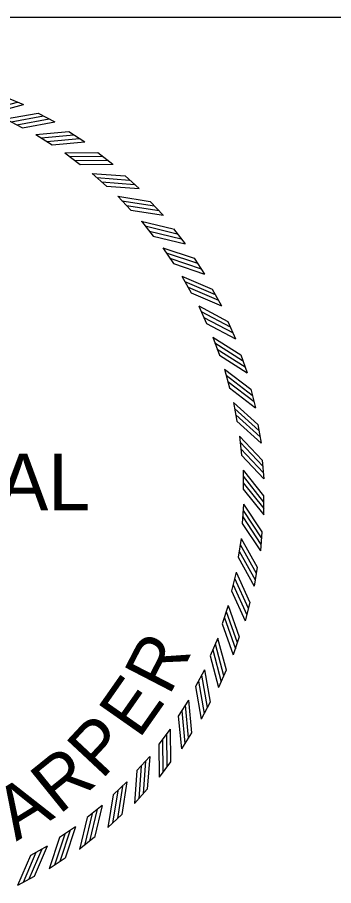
# Model space of a CAD drawing. Extents: x 16 to 1228740, y 11 to 152440.
# Drawn here: x 17.7982 to 17.8608, y 10.8266 to 10.9986 of the extents above; entities that cross this region are included whole.
import ezdxf

# ---------------------------------------------------------------- set-up
doc = ezdxf.new("R2010")
doc.units = 0
doc.layers.add('R_No Plot', color=7, linetype='Continuous')
doc.layers.add('STAMP_FRED', color=7, linetype='Continuous')

msp = doc.modelspace()

# ---------------------------------------------------------------- linework, layer by layer
at = {"layer": 'R_No Plot'}
msp.add_line((17.888, 10.99864), (17.47349, 10.99864), dxfattribs=at)
at = {"layer": 'STAMP_FRED'}
for p, q in [((17.79591, 10.98283), (17.79938, 10.98135)), ((17.79585, 10.97854), (17.79919, 10.97677)), ((17.80228, 10.97968), (17.80561, 10.97791)), ((17.80187, 10.9754), (17.80505, 10.97337)), ((17.80836, 10.97601), (17.81154, 10.97398)), ((17.8076, 10.97178), (17.81061, 10.96949)), ((17.81413, 10.97185), (17.81712, 10.96956)), ((17.81302, 10.9677), (17.81582, 10.96517)), ((17.81952, 10.96723), (17.82232, 10.9647)), ((17.81808, 10.96319), (17.82066, 10.96043)), ((17.82452, 10.96218), (17.8271, 10.95943)), ((17.82275, 10.95827), (17.8251, 10.95531)), ((17.82909, 10.95673), (17.83143, 10.95378)), ((17.827, 10.95298), (17.82909, 10.94984)), ((17.83319, 10.95093), (17.83528, 10.94779)), ((17.83079, 10.94737), (17.83262, 10.94406)), ((17.83679, 10.94481), (17.83862, 10.94151)), ((17.83411, 10.94145), (17.83566, 10.93801)), ((17.83988, 10.93841), (17.84143, 10.93497)), ((17.83694, 10.93529), (17.8382, 10.93172)), ((17.84243, 10.93177), (17.84369, 10.92822)), ((17.83924, 10.92891), (17.8402, 10.92525)), ((17.84443, 10.92495), (17.84538, 10.92131)), ((17.841, 10.92236), (17.84166, 10.91864)), ((17.84585, 10.91799), (17.8465, 10.91428)), ((17.84222, 10.91569), (17.84257, 10.91193)), ((17.84669, 10.91093), (17.84704, 10.90718)), ((17.84289, 10.90894), (17.84292, 10.90516)), ((17.84695, 10.90383), (17.84698, 10.90006)), ((17.843, 10.90216), (17.84272, 10.89839)), ((17.84662, 10.89673), (17.84634, 10.89297)), ((17.84254, 10.89539), (17.84195, 10.89166)), ((17.8457, 10.88969), (17.84512, 10.88596)), ((17.84153, 10.88869), (17.84064, 10.88501)), ((17.83997, 10.88209), (17.83877, 10.8785)), ((17.84421, 10.88274), (17.84332, 10.87908)), ((17.83787, 10.87564), (17.83638, 10.87216)), ((17.84215, 10.87594), (17.84096, 10.87236)), ((17.83524, 10.86939), (17.83347, 10.86605)), ((17.83953, 10.86933), (17.83805, 10.86587)), ((17.8321, 10.86337), (17.83007, 10.86019)), ((17.83638, 10.86296), (17.83461, 10.85963)), ((17.82848, 10.85764), (17.82619, 10.85464)), ((17.83271, 10.85688), (17.83068, 10.8537)), ((17.8244, 10.85222), (17.82187, 10.84942)), ((17.82855, 10.85112), (17.82626, 10.84812)), ((17.81989, 10.84716), (17.81713, 10.84458)), ((17.82393, 10.84572), (17.8214, 10.84292)), ((17.81497, 10.84249), (17.81201, 10.84014)), ((17.81888, 10.84072), (17.81613, 10.83814)), ((17.80968, 10.83824), (17.80654, 10.83615)), ((17.81343, 10.83615), (17.81048, 10.83381)), ((17.80407, 10.83445), (17.80076, 10.83262)), ((17.80763, 10.83205), (17.80449, 10.82996)), ((17.80151, 10.82845), (17.79821, 10.82662))]:
    msp.add_line(p, q, dxfattribs=at)
for points in [[(17.79192, 10.98019), (17.79823, 10.98185)], [(17.79307, 10.97968), (17.79938, 10.98135)], [(17.79585, 10.97854), (17.80227, 10.97968)], [(17.79692, 10.97796), (17.80334, 10.9791)], [(17.79809, 10.97737), (17.80451, 10.97851)], [(17.79919, 10.97678), (17.80561, 10.97791)], [(17.80186, 10.9754), (17.80836, 10.97601)], [(17.80288, 10.97474), (17.80937, 10.97535)], [(17.804, 10.97406), (17.81049, 10.97466)], [(17.80505, 10.97337), (17.81154, 10.97398)], [(17.8076, 10.97178), (17.81412, 10.97185)], [(17.80855, 10.97104), (17.81508, 10.97111)], [(17.80961, 10.97027), (17.81613, 10.97033)], [(17.8106, 10.9695), (17.81713, 10.96956)], [(17.81301, 10.9677), (17.81952, 10.96723)], [(17.81391, 10.96688), (17.82041, 10.96641)], [(17.8149, 10.96603), (17.8214, 10.96555)], [(17.81582, 10.96517), (17.82233, 10.9647)], [(17.81807, 10.96319), (17.82452, 10.96218)], [(17.81889, 10.9623), (17.82534, 10.96129)], [(17.81981, 10.96136), (17.82626, 10.96035)], [(17.82066, 10.96044), (17.82711, 10.95943)], [(17.82274, 10.95827), (17.82908, 10.95674)], [(17.82349, 10.95731), (17.82983, 10.95578)], [(17.82433, 10.95631), (17.83066, 10.95477)], [(17.8251, 10.95532), (17.83144, 10.95378)], [(17.82699, 10.95299), (17.83318, 10.95093)], [(17.82766, 10.95197), (17.83385, 10.94992)], [(17.82841, 10.9509), (17.8346, 10.94884)], [(17.82909, 10.94985), (17.83528, 10.94779)], [(17.83079, 10.94737), (17.83679, 10.94481)], [(17.83137, 10.9463), (17.83737, 10.94374)], [(17.83203, 10.94517), (17.83803, 10.94261)], [(17.83262, 10.94406), (17.83862, 10.94151)], [(17.83411, 10.94146), (17.83988, 10.93841)], [(17.8346, 10.94034), (17.84037, 10.9373)], [(17.83516, 10.93916), (17.84093, 10.93612)], [(17.83567, 10.93801), (17.84143, 10.93497)], [(17.83693, 10.93529), (17.84243, 10.93178)], [(17.83732, 10.93414), (17.84282, 10.93063)], [(17.83779, 10.93292), (17.84329, 10.9294)], [(17.8382, 10.93173), (17.84369, 10.92822)], [(17.83923, 10.92891), (17.84442, 10.92496)], [(17.83953, 10.92773), (17.84472, 10.92378)], [(17.83989, 10.92647), (17.84508, 10.92252)], [(17.8402, 10.92526), (17.84539, 10.9213)], [(17.841, 10.92236), (17.84584, 10.91799)], [(17.8412, 10.92117), (17.84604, 10.9168)], [(17.84146, 10.91988), (17.8463, 10.91551)], [(17.84166, 10.91864), (17.84651, 10.91427)], [(17.84222, 10.91569), (17.84669, 10.91094)], [(17.84232, 10.91448), (17.84679, 10.90973)], [(17.84247, 10.91318), (17.84694, 10.90843)], [(17.84257, 10.91193), (17.84704, 10.90718)], [(17.84289, 10.90894), (17.84695, 10.90384)], [(17.84289, 10.90773), (17.84695, 10.90262)], [(17.84293, 10.90642), (17.84699, 10.90131)], [(17.84293, 10.90517), (17.84699, 10.90006)], [(17.84289, 10.90095), (17.84652, 10.89553)], [(17.84299, 10.90216), (17.84662, 10.89674)], [(17.84283, 10.89965), (17.84645, 10.89422)], [(17.84272, 10.89839), (17.84634, 10.89297)], [(17.84234, 10.8942), (17.8455, 10.8885)], [(17.84254, 10.8954), (17.8457, 10.88969)], [(17.84216, 10.8929), (17.84533, 10.8872)], [(17.84196, 10.89166), (17.84512, 10.88596)], [(17.84123, 10.88752), (17.84391, 10.88157)], [(17.84153, 10.88869), (17.84421, 10.88274)], [(17.84095, 10.88624), (17.84363, 10.88029)], [(17.84064, 10.88502), (17.84332, 10.87907)], [(17.83997, 10.88209), (17.84215, 10.87594)], [(17.83957, 10.88094), (17.84175, 10.8748)], [(17.83878, 10.87851), (17.84096, 10.87236)], [(17.83919, 10.87969), (17.84137, 10.87355)], [(17.83786, 10.87564), (17.83953, 10.86934)], [(17.83689, 10.87332), (17.83855, 10.86701)], [(17.83738, 10.87453), (17.83904, 10.86823)], [(17.83638, 10.87217), (17.83805, 10.86586)], [(17.83466, 10.86833), (17.8358, 10.8619)], [(17.83524, 10.86939), (17.83638, 10.86297)], [(17.83407, 10.86715), (17.83521, 10.86073)], [(17.83348, 10.86605), (17.83461, 10.85963)], [(17.8321, 10.86338), (17.83271, 10.85688)], [(17.83076, 10.86124), (17.83136, 10.85475)], [(17.83144, 10.86236), (17.83204, 10.85587)], [(17.83007, 10.86019), (17.83068, 10.8537)], [(17.82774, 10.85669), (17.82781, 10.85016)], [(17.82848, 10.85764), (17.82855, 10.85112)], [(17.8262, 10.85464), (17.82626, 10.84811)], [(17.82697, 10.85563), (17.82703, 10.84911)], [(17.82358, 10.85134), (17.82311, 10.84483)], [(17.8244, 10.85223), (17.82393, 10.84572)], [(17.82187, 10.84942), (17.8214, 10.84291)], [(17.82272, 10.85034), (17.82225, 10.84384)], [(17.819, 10.84635), (17.81799, 10.8399)], [(17.81989, 10.84717), (17.81888, 10.84072)], [(17.81714, 10.84458), (17.81613, 10.83813)], [(17.81806, 10.84543), (17.81705, 10.83898)], [(17.81497, 10.8425), (17.81344, 10.83616)], [(17.81301, 10.84092), (17.81147, 10.83458)], [(17.81401, 10.84175), (17.81248, 10.83541)], [(17.81202, 10.84014), (17.81048, 10.8338)], [(17.80867, 10.83759), (17.80662, 10.83139)], [(17.80969, 10.83825), (17.80763, 10.83206)], [(17.80655, 10.83615), (17.80449, 10.82996)], [(17.8076, 10.83683), (17.80554, 10.83064)], [(17.803, 10.83387), (17.80044, 10.82787)], [(17.80407, 10.83445), (17.80151, 10.82845)], [(17.80076, 10.83262), (17.79821, 10.82662)], [(17.80187, 10.83321), (17.79931, 10.82721)]]:
    msp.add_lwpolyline(points, dxfattribs=at)

# ---------------------------------------------------------------- texts
msp.add_text('PROFESSIONAL', height=0.0111934, dxfattribs=at).set_placement((17.69618, 10.901))
for s, rotation, p in [('R', 62.6418, (17.82825, 10.86405)), ('E', 54.981, (17.82229, 10.85549)), ('P', 46.9554, (17.81488, 10.84746)), ('R', 38.9298, (17.80643, 10.84054)), ('A', 31.6338, (17.79797, 10.83533))]:
    msp.add_text(s, height=0.01042, rotation=rotation, dxfattribs=at).set_placement(p)

doc.saveas('drawing.dxf')
